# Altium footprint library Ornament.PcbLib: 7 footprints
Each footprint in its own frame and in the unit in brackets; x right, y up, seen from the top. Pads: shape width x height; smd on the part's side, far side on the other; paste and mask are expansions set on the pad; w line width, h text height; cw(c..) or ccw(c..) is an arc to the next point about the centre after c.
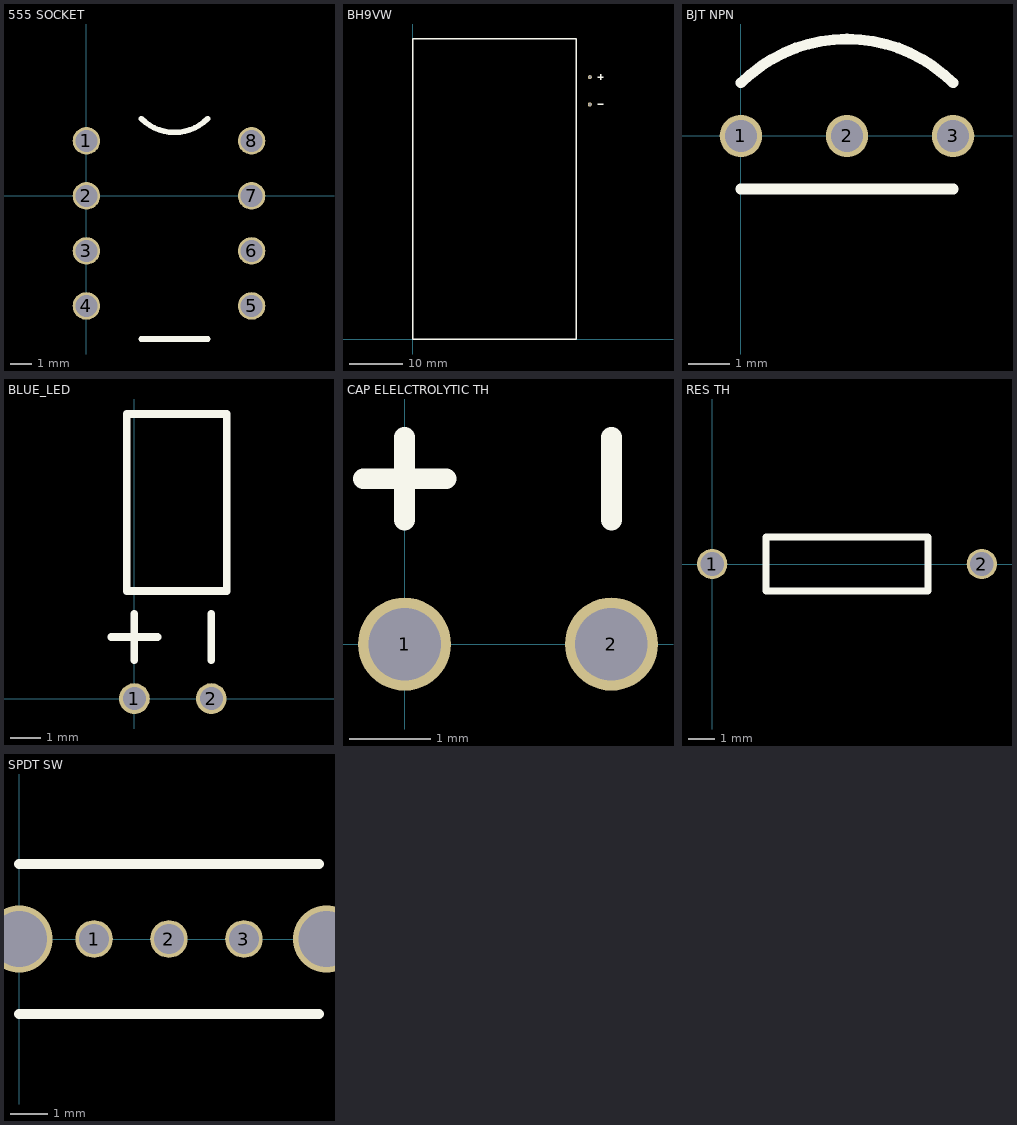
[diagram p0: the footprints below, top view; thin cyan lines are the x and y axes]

## 555 SOCKET [mil] "1-2199298-2"
pads (8):
  round 50 hole 40: 1(0,100) 2(0,0) 3(0,-100) 4(0,-200) 5(300,-200) 6(300,-100) 7(300,0) 8(300,100)
Top Overlay:
  lines w10: 100,-260 220,-260 ; 100,140 ccw(c160,200) 220,140

## BH9VW [mil] "BH9VPC 9V Battery Holder Leaded"
height 826.77
pads (2):
  round 30 hole 22: 1(1300,1920) 2(1300,1720)
Top Overlay:
  lines w10: 1360,1720 1400,1720 ; 1360,1920 1400,1920 ; 1380,1900 1380,1940 ; 0,0 0,2200 1200,2200 1200,0 0,0

## BJT NPN [mil]
pads (3):
  round 40 hole 30: 1(0,0) 2(100,0) 3(200,0)
Top Overlay:
  lines w10: 0,-50 200,-50 ; 0,50 cw(c100,-50) 200,50

## BLUE_LED [mil]
pads (2):
  round 40 hole 30: 1(0,0) 2(100,0)
Top Overlay:
  lines w10: -30,80 30,80 ; 0,50 0,110 ; 100,50 100,110 ; -10,140 120,140 120,370 -10,370 -10,140

## CAP ELELCTROLYTIC TH [mil]
pads (2):
  round 45 hole 35: 1(0,0) 2(100,0)
Top Overlay:
  lines w10: 0,100 0,80 ; 100,60 100,80 100,100 ; 0,80 0,60 0,80 ; 0,80 20,80 -20,80 0,80

## RES TH [mil] "RES TH 400MIL"
pads (2):
  round 45 hole 35: 1(0,0) 2(400,0)
Top Overlay:
  lines w10: 80,-40 320,-40 320,40 80,40 80,0 80,-40

## SPDT SW [mm]
pads (3):
  round 1 hole 0.8: 1(2,0) 2(4,0) 3(6,0)
via 8.2,0 diameter 1.778 hole 1.5
via 0,0 diameter 1.778 hole 1.5
Top Overlay:
  lines w0.254: 0,-2 8,-2 ; 0,2 8,2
